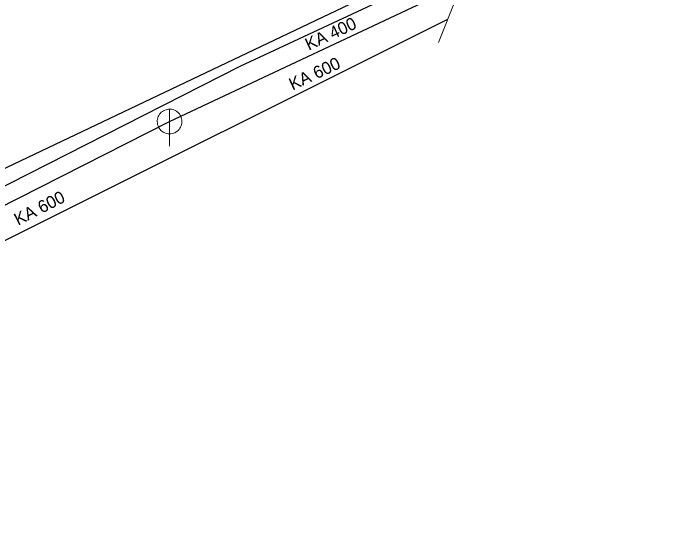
# Model space of a CAD drawing. Extents: x -690535 to -689974, y -975624 to -975325.
# Drawn here: x -690368.9 to -690316.2, y -975523.3 to -975480.2 of the extents above; entities that cross this region are included whole.
import ezdxf

# ---------------------------------------------------------------- set-up
doc = ezdxf.new("R2010")
doc.units = 0
doc.header["$LTSCALE"] = 0.4
for name, color, linetype, lineweight in [('1', 7, 'Continuous', 13), ('11', 7, 'Continuous', 13), ('14', 7, 'Continuous', 25), ('17', 7, 'Continuous', 25), ('22', 7, 'Continuous', 13)]:
    doc.layers.add(name, color=color, linetype=linetype, lineweight=lineweight)

msp = doc.modelspace()

# ---------------------------------------------------------------- linework, layer by layer
at = {"layer": '11'}
msp.add_line((-690334.41, -975482.64), (-690332.539, -975477.879), dxfattribs=at)
at = {"layer": '14'}
for p, q in [((-690369.923, -975493.022), (-690316.232, -975467.417)), ((-690392.036, -975509.912), (-690333.67, -975480.756))]:
    msp.add_line(p, q, dxfattribs=at)
msp.add_lwpolyline([(-690419.82, -975520.71), (-690394.789, -975508.03), (-690391.289, -975506.52), (-690377.19, -975499.69), (-690356.199, -975489.039), (-690332.539, -975477.879), (-690325.927, -975474.555)], dxfattribs=at)
at = {"layer": '17'}
msp.add_lwpolyline([(-690487.124, -975551.552), (-690473.512, -975544.629), (-690473.092, -975544.418), (-690468.651, -975542.14), (-690430.232, -975523.675), (-690404.89, -975511.94), (-690401.289, -975510.34), (-690387.871, -975503.577), (-690350.486, -975484.551), (-690338.608, -975478.999)], dxfattribs=at)
at = {"layer": '22'}
msp.add_line((-690356.2, -975491.04), (-690356.199, -975488.04), dxfattribs=at)
msp.add_lwpolyline([(-690355.2, -975489.04), (-690355.205, -975488.931), (-690355.223, -975488.823), (-690355.253, -975488.717), (-690355.293, -975488.616), (-690355.345, -975488.519), (-690355.407, -975488.429), (-690355.479, -975488.346), (-690355.559, -975488.272), (-690355.647, -975488.206), (-690355.741, -975488.151), (-690355.841, -975488.106), (-690355.946, -975488.073), (-690356.053, -975488.051), (-690356.162, -975488.041), (-690356.272, -975488.043), (-690356.38, -975488.057), (-690356.487, -975488.082), (-690356.59, -975488.119), (-690356.688, -975488.168), (-690356.78, -975488.226), (-690356.866, -975488.295), (-690356.943, -975488.372), (-690357.012, -975488.458), (-690357.071, -975488.55), (-690357.119, -975488.648), (-690357.156, -975488.751), (-690357.182, -975488.858), (-690357.196, -975488.966), (-690357.199, -975489.076), (-690357.189, -975489.185), (-690357.168, -975489.292), (-690357.134, -975489.396), (-690357.09, -975489.496), (-690357.035, -975489.591), (-690356.969, -975489.679), (-690356.895, -975489.759), (-690356.812, -975489.831), (-690356.722, -975489.893), (-690356.626, -975489.945), (-690356.524, -975489.986), (-690356.419, -975490.016), (-690356.311, -975490.034), (-690356.201, -975490.04), (-690356.092, -975490.034), (-690355.984, -975490.016), (-690355.879, -975489.987), (-690355.777, -975489.946), (-690355.68, -975489.894), (-690355.59, -975489.832), (-690355.507, -975489.761), (-690355.432, -975489.681), (-690355.367, -975489.593), (-690355.311, -975489.499), (-690355.267, -975489.399), (-690355.233, -975489.295), (-690355.211, -975489.187), (-690355.201, -975489.078)], close=True, dxfattribs=at)

# ---------------------------------------------------------------- texts
at = {"layer": '1'}
for s, rotation, p in [('KA 400', 25, (-690344.93, -975483.302)), ('KA 600', 25, (-690346.236, -975486.535)), ('KA 600', 27, (-690368.471, -975497.492))]:
    msp.add_text(s, height=1, rotation=rotation, dxfattribs=at).set_placement(p)

doc.saveas('drawing.dxf')
